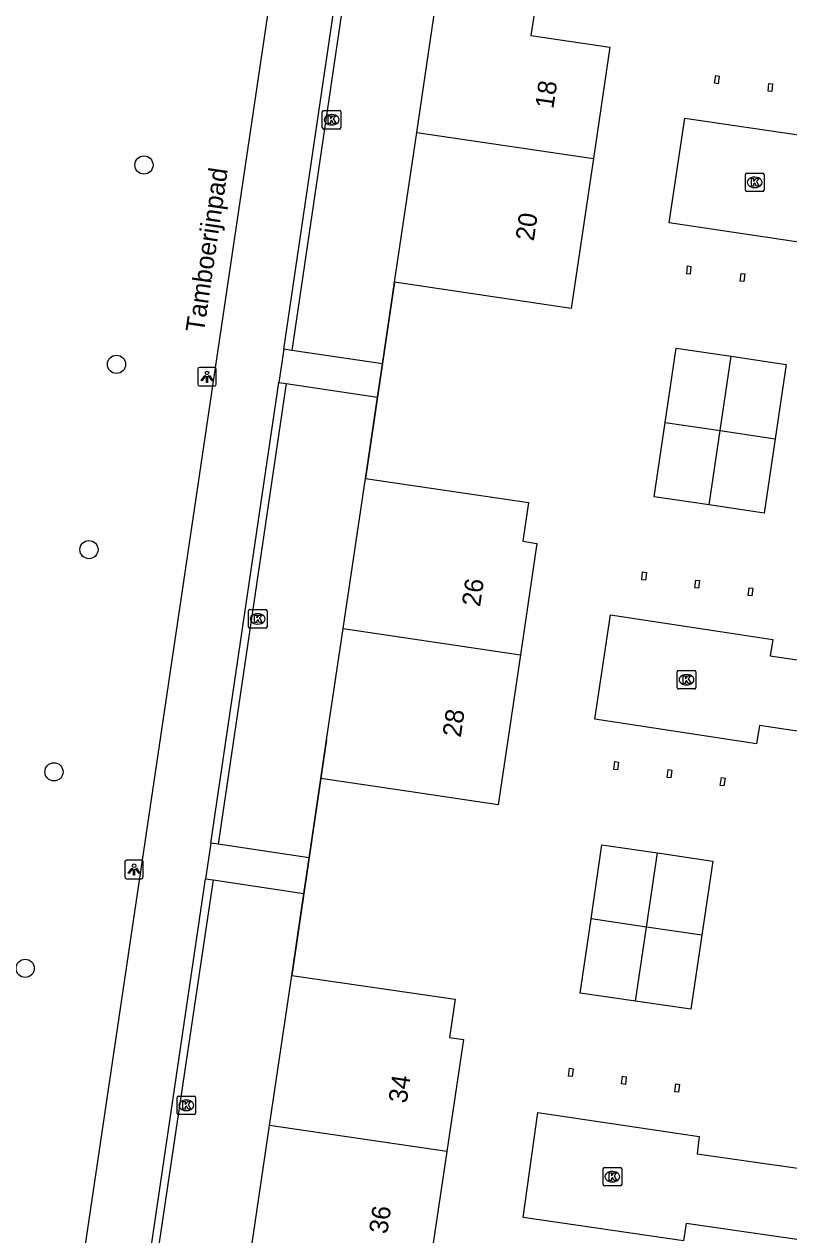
# Model space of a CAD drawing. Extents: x 164150 to 165261, y 382513 to 383432.
# Drawn here: x 164487.7 to 164528.8, y 383053.9 to 383119 of the extents above; entities that cross this region are included whole.
import ezdxf

# ---------------------------------------------------------------- set-up
doc = ezdxf.new("R2010")
doc.units = 0
for name, color, linetype in [('IMGEO_Boom', 7, 'Continuous'), ('IMGEO_Groenvoorziening', 7, 'Continuous'), ('IMGEO_Haag', 7, 'Continuous'), ('IMGEO_Kolk', 7, 'Continuous'), ('IMGEO_Lichtpunt', 7, 'Continuous'), ('IMGEO_Muur', 7, 'Continuous'), ('IMGEO_Openbare_ruimte_label', 7, 'Continuous'), ('IMGEO_Pand', 7, 'Continuous'), ('IMGEO_Pand_nummerreeks', 7, 'Continuous'), ('IMGEO_Rijbaan_lokaal_open', 7, 'Continuous'), ('IMGEO_Voetpad_gesloten', 7, 'Continuous'), ('IMGEO_Voetpad_halfverhard', 7, 'Continuous')]:
    doc.layers.add(name, color=color, linetype=linetype)

msp = doc.modelspace()

# ---------------------------------------------------------------- linework, layer by layer
at = {"layer": 'IMGEO_Boom'}
for centre in [(164494.134, 383111.442), (164492.657, 383100.718), (164491.176, 383090.751), (164489.291, 383078.792), (164487.744, 383068.223)]:
    msp.add_circle(centre, 0.489, dxfattribs=at)
at = {"layer": 'IMGEO_Groenvoorziening'}
for points in [[(164506.966, 383100.742), (164507.618, 383105.137)], [(164506.052, 383094.577), (164506.702, 383098.96)], [(164503.026, 383074.173), (164503.654, 383078.431)], [(164502.091, 383067.84), (164502.743, 383072.256)]]:
    msp.add_lwpolyline(points, dxfattribs=at)
at = {"layer": 'IMGEO_Haag'}
for points in [[(164505.769, 383126.423), (164502.086, 383101.466)], [(164501.792, 383099.688), (164498.132, 383074.895)], [(164497.85, 383072.978), (164494.335, 383049.373)]]:
    msp.add_lwpolyline(points, dxfattribs=at)
at = {"layer": 'IMGEO_Kolk'}
for p, q in [((164503.729, 383113.453), (164503.729, 383114.305)), ((164503.804, 383114.379), (164504.656, 383114.379)), ((164504.217, 383114.159), (164504.242, 383114.159)), ((164504.73, 383114.305), (164504.73, 383113.453)), ((164504.656, 383113.379), (164503.804, 383113.379)), ((164504.24, 383113.599), (164504.215, 383113.599)), ((164526.493, 383110.083), (164526.493, 383110.935)), ((164526.568, 383111.009), (164527.42, 383111.009)), ((164526.981, 383110.789), (164527.006, 383110.789)), ((164527.494, 383110.935), (164527.494, 383110.083)), ((164527.42, 383110.009), (164526.568, 383110.009)), ((164527.004, 383110.229), (164526.979, 383110.229)), ((164499.756, 383086.597), (164499.756, 383087.449)), ((164499.831, 383087.523), (164500.683, 383087.523)), ((164500.244, 383087.303), (164500.269, 383087.303)), ((164500.757, 383087.449), (164500.757, 383086.597)), ((164500.267, 383086.743), (164500.242, 383086.743)), ((164500.683, 383086.523), (164499.831, 383086.523)), ((164522.824, 383083.324), (164522.824, 383084.176)), ((164522.899, 383084.25), (164523.751, 383084.25)), ((164523.312, 383084.03), (164523.337, 383084.03)), ((164523.825, 383084.176), (164523.825, 383083.324)), ((164523.335, 383083.47), (164523.31, 383083.47)), ((164523.751, 383083.25), (164522.899, 383083.25)), ((164495.914, 383060.424), (164495.914, 383061.276)), ((164495.989, 383061.35), (164496.841, 383061.35)), ((164496.915, 383061.276), (164496.915, 383060.424)), ((164496.425, 383060.57), (164496.4, 383060.57)), ((164496.402, 383061.13), (164496.427, 383061.13)), ((164496.841, 383060.35), (164495.989, 383060.35)), ((164518.837, 383056.585), (164518.837, 383057.437)), ((164518.912, 383057.511), (164519.764, 383057.511)), ((164519.325, 383057.291), (164519.35, 383057.291)), ((164519.838, 383057.437), (164519.838, 383056.585)), ((164519.348, 383056.731), (164519.323, 383056.731)), ((164519.764, 383056.511), (164518.912, 383056.511))]:
    msp.add_line(p, q, dxfattribs=at)
for points in [[(164503.729, 383113.453), (164503.729, 383114.305)], [(164503.804, 383114.379), (164504.656, 383114.379)], [(164504.05, 383114.079), (164504.173, 383114.079), (164504.173, 383113.928), (164504.303, 383114.079), (164504.467, 383114.079), (164504.321, 383113.928), (164504.474, 383113.679), (164504.322, 383113.679), (164504.237, 383113.843), (164504.173, 383113.776), (164504.173, 383113.679), (164504.05, 383113.679), (164504.05, 383114.079)], [(164504.73, 383114.305), (164504.73, 383113.453)], [(164504.656, 383113.379), (164503.804, 383113.379)], [(164526.493, 383110.083), (164526.493, 383110.935)], [(164526.568, 383111.009), (164527.42, 383111.009)], [(164526.814, 383110.709), (164526.937, 383110.709), (164526.937, 383110.558), (164527.067, 383110.709), (164527.231, 383110.709), (164527.085, 383110.558), (164527.238, 383110.309), (164527.086, 383110.309), (164527.001, 383110.473), (164526.937, 383110.406), (164526.937, 383110.309), (164526.814, 383110.309), (164526.814, 383110.709)], [(164527.494, 383110.935), (164527.494, 383110.083)], [(164527.42, 383110.009), (164526.568, 383110.009)], [(164499.756, 383086.597), (164499.756, 383087.449)], [(164499.831, 383087.523), (164500.683, 383087.523)], [(164500.077, 383087.223), (164500.2, 383087.223), (164500.2, 383087.072), (164500.33, 383087.223), (164500.494, 383087.223), (164500.348, 383087.072), (164500.501, 383086.823), (164500.349, 383086.823), (164500.264, 383086.987), (164500.2, 383086.92), (164500.2, 383086.823), (164500.077, 383086.823), (164500.077, 383087.223)], [(164500.757, 383087.449), (164500.757, 383086.597)], [(164500.683, 383086.523), (164499.831, 383086.523)], [(164522.824, 383083.324), (164522.824, 383084.176)], [(164522.899, 383084.25), (164523.751, 383084.25)], [(164523.145, 383083.95), (164523.268, 383083.95), (164523.268, 383083.799), (164523.398, 383083.95), (164523.562, 383083.95), (164523.416, 383083.799), (164523.569, 383083.55), (164523.417, 383083.55), (164523.332, 383083.714), (164523.268, 383083.647), (164523.268, 383083.55), (164523.145, 383083.55), (164523.145, 383083.95)], [(164523.825, 383084.176), (164523.825, 383083.324)], [(164523.751, 383083.25), (164522.899, 383083.25)], [(164495.914, 383060.424), (164495.914, 383061.276)], [(164495.989, 383061.35), (164496.841, 383061.35)], [(164496.915, 383061.276), (164496.915, 383060.424)], [(164496.235, 383061.05), (164496.358, 383061.05), (164496.358, 383060.899), (164496.488, 383061.05), (164496.652, 383061.05), (164496.506, 383060.899), (164496.659, 383060.65), (164496.507, 383060.65), (164496.422, 383060.814), (164496.358, 383060.747), (164496.358, 383060.65), (164496.235, 383060.65), (164496.235, 383061.05)], [(164496.841, 383060.35), (164495.989, 383060.35)], [(164518.837, 383056.585), (164518.837, 383057.437)], [(164518.912, 383057.511), (164519.764, 383057.511)], [(164519.838, 383057.437), (164519.838, 383056.585)], [(164519.158, 383057.211), (164519.281, 383057.211), (164519.281, 383057.06), (164519.411, 383057.211), (164519.575, 383057.211), (164519.429, 383057.06), (164519.582, 383056.811), (164519.43, 383056.811), (164519.345, 383056.975), (164519.281, 383056.908), (164519.281, 383056.811), (164519.158, 383056.811), (164519.158, 383057.211)], [(164519.764, 383056.511), (164518.912, 383056.511)]]:
    msp.add_lwpolyline(points, dxfattribs=at)
for centre, start, end in [((164503.806, 383114.303), 91.55205, 178.44795), ((164503.806, 383114.303), 91.55205, 178.44795), ((164504.654, 383114.303), 1.55205, 88.44795), ((164504.654, 383114.303), 1.55205, 88.44795), ((164503.806, 383113.455), 181.55205, 268.44795), ((164503.806, 383113.455), 181.55205, 268.44795), ((164504.654, 383113.455), 271.55205, 358.44795), ((164504.654, 383113.455), 271.55205, 358.44795), ((164526.57, 383110.933), 91.55205, 178.44795), ((164526.57, 383110.933), 91.55205, 178.44795), ((164527.418, 383110.933), 1.55205, 88.44795), ((164527.418, 383110.933), 1.55205, 88.44795), ((164526.57, 383110.085), 181.55205, 268.44795), ((164526.57, 383110.085), 181.55205, 268.44795), ((164527.418, 383110.085), 271.55205, 358.44795), ((164527.418, 383110.085), 271.55205, 358.44795), ((164499.833, 383087.447), 91.55205, 178.44795), ((164499.833, 383087.447), 91.55205, 178.44795), ((164500.681, 383087.447), 1.55205, 88.44795), ((164500.681, 383087.447), 1.55205, 88.44795), ((164499.833, 383086.599), 181.55205, 268.44795), ((164499.833, 383086.599), 181.55205, 268.44795), ((164500.681, 383086.599), 271.55205, 358.44795), ((164500.681, 383086.599), 271.55205, 358.44795), ((164522.901, 383084.174), 91.55205, 178.44795), ((164522.901, 383084.174), 91.55205, 178.44795), ((164523.749, 383084.174), 1.55205, 88.44795), ((164523.749, 383084.174), 1.55205, 88.44795), ((164522.901, 383083.326), 181.55205, 268.44795), ((164522.901, 383083.326), 181.55205, 268.44795), ((164523.749, 383083.326), 271.55205, 358.44795), ((164523.749, 383083.326), 271.55205, 358.44795), ((164495.991, 383061.274), 91.55205, 178.44795), ((164495.991, 383061.274), 91.55205, 178.44795), ((164496.839, 383061.274), 1.55205, 88.44795), ((164496.839, 383061.274), 1.55205, 88.44795), ((164495.991, 383060.426), 181.55205, 268.44795), ((164495.991, 383060.426), 181.55205, 268.44795), ((164496.839, 383060.426), 271.55205, 358.44795), ((164496.839, 383060.426), 271.55205, 358.44795), ((164518.914, 383057.435), 91.55205, 178.44795), ((164518.914, 383057.435), 91.55205, 178.44795), ((164519.762, 383057.435), 1.55205, 88.44795), ((164519.762, 383057.435), 1.55205, 88.44795), ((164518.914, 383056.587), 181.55205, 268.44795), ((164518.914, 383056.587), 181.55205, 268.44795), ((164519.762, 383056.587), 271.55205, 358.44795), ((164519.762, 383056.587), 271.55205, 358.44795)]:
    msp.add_arc(centre, 0.0765, start, end, dxfattribs=at)
for centre, major_axis, ratio, start_param, end_param in [((164504.216, 383113.879), (-0.387, 0.002), 0.722429, 4.712389, 7.853982), ((164504.241, 383113.879), (-0.39, 0.002), 0.717154, 1.570796, 4.712389), ((164526.98, 383110.509), (-0.387, 0.002), 0.722429, 4.712389, 7.853982), ((164527.005, 383110.509), (-0.39, 0.002), 0.717154, 1.570796, 4.712389), ((164500.243, 383087.023), (-0.387, 0.002), 0.722429, 4.712389, 7.853982), ((164500.268, 383087.023), (-0.39, 0.002), 0.717154, 1.570796, 4.712389), ((164523.311, 383083.75), (-0.387, 0.002), 0.722429, 4.712389, 7.853982), ((164523.336, 383083.75), (-0.39, 0.002), 0.717154, 1.570796, 4.712389), ((164496.401, 383060.85), (-0.387, 0.002), 0.722429, 4.712389, 7.853982), ((164496.426, 383060.85), (-0.39, 0.002), 0.717154, 1.570796, 4.712389), ((164519.324, 383057.011), (-0.387, 0.002), 0.722429, 4.712389, 7.853982), ((164519.349, 383057.011), (-0.39, 0.002), 0.717154, 1.570796, 4.712389)]:
    msp.add_ellipse(centre, major_axis=major_axis, ratio=ratio, start_param=start_param, end_param=end_param, dxfattribs=at)
at = {"layer": 'IMGEO_Lichtpunt'}
for p, q in [((164497.029, 383100.454), (164497.029, 383099.647)), ((164497.029, 383100.454), (164497.029, 383099.647)), ((164497.931, 383100.549), (164497.123, 383100.549)), ((164497.931, 383100.549), (164497.123, 383100.549)), ((164498.025, 383099.647), (164498.025, 383100.454)), ((164498.025, 383099.647), (164498.025, 383100.454)), ((164497.123, 383099.553), (164497.931, 383099.553)), ((164497.123, 383099.553), (164497.931, 383099.553)), ((164493.104, 383073.944), (164493.104, 383073.137)), ((164493.104, 383073.944), (164493.104, 383073.137)), ((164494.006, 383074.039), (164493.198, 383074.039)), ((164494.006, 383074.039), (164493.198, 383074.039)), ((164494.1, 383073.137), (164494.1, 383073.944)), ((164494.1, 383073.137), (164494.1, 383073.944)), ((164493.198, 383073.043), (164494.006, 383073.043)), ((164493.198, 383073.043), (164494.006, 383073.043))]:
    msp.add_line(p, q, dxfattribs=at)
for points in [[(164497.403, 383100.118), (164497.442, 383100.09), (164497.254, 383099.828), (164497.216, 383099.855), (164497.403, 383100.118)], [(164497.505, 383100.07), (164497.552, 383100.07), (164497.552, 383099.748), (164497.505, 383099.748), (164497.505, 383100.07)], [(164497.615, 383100.09), (164497.653, 383100.117), (164497.84, 383099.855), (164497.801, 383099.827), (164497.615, 383100.09)], [(164493.478, 383073.608), (164493.517, 383073.58), (164493.329, 383073.318), (164493.291, 383073.345), (164493.478, 383073.608)], [(164493.58, 383073.56), (164493.627, 383073.56), (164493.627, 383073.238), (164493.58, 383073.238), (164493.58, 383073.56)], [(164493.69, 383073.58), (164493.728, 383073.607), (164493.915, 383073.345), (164493.876, 383073.317), (164493.69, 383073.58)]]:
    msp.add_lwpolyline(points, dxfattribs=at)
for centre in [(164497.528, 383100.252), (164493.603, 383073.742)]:
    msp.add_circle(centre, 0.0994, dxfattribs=at)
for centre, start, end in [((164497.123, 383100.454), 90, 180), ((164497.123, 383100.454), 90, 180), ((164497.931, 383100.454), 0, 90), ((164497.931, 383100.454), 0, 90), ((164497.123, 383099.647), 180, 270), ((164497.123, 383099.647), 180, 270), ((164497.931, 383099.647), 270, 0), ((164497.931, 383099.647), 270, 360), ((164493.198, 383073.944), 90, 180), ((164493.198, 383073.944), 90, 180), ((164494.006, 383073.944), 0, 90), ((164494.006, 383073.944), 0, 90), ((164493.198, 383073.137), 180, 270), ((164493.198, 383073.137), 180, 270), ((164494.006, 383073.137), 270, 0), ((164494.006, 383073.137), 270, 360)]:
    msp.add_arc(centre, 0.0946, start, end, dxfattribs=at)
at = {"layer": 'IMGEO_Muur'}
for points in [[(164507.618, 383105.137), (164506.052, 383094.577)], [(164503.963, 383080.511), (164502.091, 383067.84)]]:
    msp.add_lwpolyline(points, dxfattribs=at)
at = {"layer": 'IMGEO_Pand'}
for points in [[(164508.808, 383113.198), (164510, 383121.27)], [(164510, 383121.27), (164515.278, 383120.494), (164514.943, 383118.407), (164519.197, 383117.78), (164518.315, 383111.794)], [(164524.835, 383115.842), (164524.899, 383116.256), (164525.084, 383116.228), (164525.02, 383115.813), (164524.835, 383115.842)], [(164527.721, 383115.418), (164527.762, 383115.832), (164527.958, 383115.812), (164527.917, 383115.399), (164527.721, 383115.418)], [(164507.618, 383105.137), (164508.808, 383113.198)], [(164508.808, 383113.198), (164518.315, 383111.794)], [(164518.315, 383111.794), (164517.127, 383103.726), (164507.618, 383105.137)], [(164523.339, 383105.59), (164523.387, 383106.01), (164523.566, 383105.99), (164523.519, 383105.57), (164523.339, 383105.59)], [(164526.219, 383105.195), (164526.27, 383105.611), (164526.463, 383105.588), (164526.412, 383105.172), (164526.219, 383105.195)], [(164522.179, 383097.595), (164522.776, 383101.595), (164525.734, 383101.154)], [(164525.137, 383097.153), (164525.734, 383101.154)], [(164525.734, 383101.154), (164528.692, 383100.712), (164528.095, 383096.712)], [(164524.54, 383093.153), (164521.582, 383093.595), (164522.179, 383097.595)], [(164522.179, 383097.595), (164525.137, 383097.153)], [(164524.54, 383093.153), (164525.137, 383097.153)], [(164525.137, 383097.153), (164528.095, 383096.712)], [(164528.095, 383096.712), (164527.498, 383092.712), (164524.54, 383093.153)], [(164504.853, 383086.506), (164506.052, 383094.577)], [(164506.052, 383094.577), (164514.826, 383093.287), (164514.52, 383091.197), (164515.272, 383091.086), (164514.385, 383085.089)], [(164520.917, 383089.122), (164520.964, 383089.545), (164521.164, 383089.523), (164521.117, 383089.1), (164520.917, 383089.122)], [(164523.775, 383088.698), (164523.82, 383089.107), (164524.02, 383089.085), (164523.975, 383088.676), (164523.775, 383088.698)], [(164526.691, 383088.697), (164526.889, 383088.676), (164526.844, 383088.257), (164526.646, 383088.278), (164526.691, 383088.697)], [(164503.654, 383078.431), (164503.963, 383080.511), (164504.853, 383086.506)], [(164504.853, 383086.506), (164514.385, 383085.089)], [(164514.385, 383085.089), (164513.192, 383077.021), (164507.909, 383077.802), (164503.654, 383078.431)], [(164519.408, 383078.922), (164519.464, 383079.344), (164519.667, 383079.317), (164519.611, 383078.895), (164519.408, 383078.922)], [(164522.285, 383078.489), (164522.34, 383078.912), (164522.53, 383078.888), (164522.475, 383078.465), (164522.285, 383078.489)], [(164525.2, 383078.481), (164525.396, 383078.452), (164525.335, 383078.035), (164525.138, 383078.064), (164525.2, 383078.481)], [(164518.188, 383070.879), (164518.771, 383074.873), (164521.756, 383074.427)], [(164521.167, 383070.439), (164521.756, 383074.427)], [(164521.756, 383074.427), (164524.741, 383073.98), (164524.145, 383069.998)], [(164520.577, 383066.451), (164517.605, 383066.885), (164518.188, 383070.879)], [(164521.167, 383070.439), (164518.188, 383070.879)], [(164520.577, 383066.451), (164521.167, 383070.439)], [(164524.145, 383069.998), (164521.167, 383070.439)], [(164524.145, 383069.998), (164523.55, 383066.016), (164520.577, 383066.451)], [(164500.898, 383059.768), (164502.091, 383067.84)], [(164502.091, 383067.84), (164510.882, 383066.566), (164510.581, 383064.495), (164511.333, 383064.383), (164510.434, 383058.359)], [(164517.227, 383062.817), (164517.169, 383062.397), (164516.968, 383062.425), (164517.027, 383062.845), (164517.227, 383062.817)], [(164520.077, 383062.392), (164520.035, 383061.979), (164519.832, 383062), (164519.874, 383062.413), (164520.077, 383062.392)], [(164522.953, 383061.975), (164522.897, 383061.558), (164522.691, 383061.585), (164522.747, 383062.004), (164522.953, 383061.975)], [(164499.711, 383051.727), (164500.898, 383059.768)], [(164510.434, 383058.359), (164500.898, 383059.768)], [(164510.434, 383058.359), (164509.235, 383050.319), (164499.711, 383051.727)]]:
    msp.add_lwpolyline(points, dxfattribs=at)
at = {"layer": 'IMGEO_Rijbaan_lokaal_open'}
for points in [[(164547.751, 383105.555), (164531.213, 383107.98), (164531.036, 383107.046), (164522.384, 383108.335), (164523.232, 383113.969), (164531.91, 383112.69), (164531.787, 383111.738), (164548.298, 383109.287)], [(164543.77, 383078.815), (164527.251, 383081.278), (164527.096, 383080.294), (164518.396, 383081.622), (164519.234, 383087.238), (164527.964, 383085.921), (164527.82, 383085.027), (164544.333, 383082.591)], [(164539.82, 383052.102), (164523.309, 383054.494), (164523.162, 383053.567), (164514.538, 383054.823), (164515.325, 383060.467), (164524.006, 383059.166), (164523.899, 383058.249), (164540.378, 383055.886)]]:
    msp.add_lwpolyline(points, dxfattribs=at)
at = {"layer": 'IMGEO_Voetpad_gesloten'}
for points in [[(164500.185, 383130.675), (164502.37, 383130.298), (164489.692, 383044.763)], [(164501.656, 383101.529), (164505.343, 383126.485)], [(164501.656, 383101.529), (164501.393, 383099.746)], [(164497.73, 383074.954), (164501.393, 383099.746)], [(164497.73, 383074.954), (164497.447, 383073.037)], [(164493.959, 383049.428), (164497.447, 383073.037)]]:
    msp.add_lwpolyline(points, dxfattribs=at)
at = {"layer": 'IMGEO_Voetpad_halfverhard'}
for points in [[(164502.086, 383101.466), (164501.656, 383101.529)], [(164506.966, 383100.742), (164502.086, 383101.466)], [(164506.702, 383098.96), (164506.966, 383100.742)], [(164501.393, 383099.746), (164501.792, 383099.688)], [(164501.792, 383099.688), (164506.702, 383098.96)], [(164498.132, 383074.895), (164497.73, 383074.954)], [(164503.026, 383074.173), (164498.132, 383074.895)], [(164502.743, 383072.256), (164503.026, 383074.173)], [(164497.447, 383073.037), (164497.85, 383072.978)], [(164497.85, 383072.978), (164502.743, 383072.256)]]:
    msp.add_lwpolyline(points, dxfattribs=at)

# ---------------------------------------------------------------- texts
at = {"layer": 'IMGEO_Openbare_ruimte_label'}
msp.add_text('Tamboerijnpad', height=1, rotation=81.65913, dxfattribs=at).set_placement((164497.358, 383102.39))
at = {"layer": 'IMGEO_Pand_nummerreeks'}
for s, rotation, p in [('18', 81.61906, (164516.157, 383114.433)), ('20', 81.61906, (164515.108, 383107.316)), ('26', 81.58759, (164512.215, 383087.642)), ('28', 81.58919, (164511.176, 383080.613)), ('34', 81.51721, (164508.269, 383060.928)), ('36', 81.51721, (164507.221, 383053.896))]:
    msp.add_text(s, height=1, rotation=rotation, dxfattribs=at).set_placement(p)

doc.saveas('drawing.dxf')
